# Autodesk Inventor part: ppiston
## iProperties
Shininess: 25.0
Length Units: 11269
Angle Units: 11279
Time Units: 11290
Mass Units: 11283
Length Display Precision: 3
Angle Display Precision: 2
Compacted: True
Created: 2001-12
Part Number: ppiston
Material: Par défaut
Document SubType Name: Modélisation
Designer: pichon
Density: 0.0
Volumn: 0.0
Area: 0.0
PropertySet Name: Model Information
Control State: 0
Master: False
Checked Out: False
Author: pichon
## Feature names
1. Révolution1 [Revolution]
2. Chanfrein1 [Chamfer]
3. Extrusion1
4. Extrusion2
